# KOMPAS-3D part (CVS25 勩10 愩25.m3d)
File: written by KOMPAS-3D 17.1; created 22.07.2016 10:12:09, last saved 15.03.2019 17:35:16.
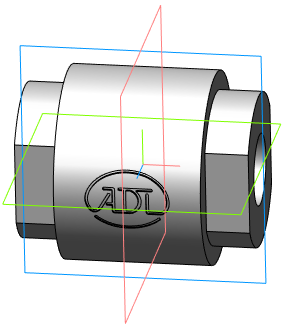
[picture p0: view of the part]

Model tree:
1. Операция без истории:3  (labels: Сталь 20  ГОСТ 1050-88)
